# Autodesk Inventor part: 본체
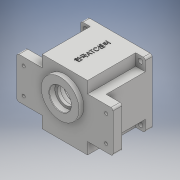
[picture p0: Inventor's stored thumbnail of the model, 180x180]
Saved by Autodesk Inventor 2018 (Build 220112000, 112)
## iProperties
Created: 2020-07
Part Number: 본체
Material: 일반
Document SubType Name: Modeling
Designer: admin
Density: 1 g/cm^3
Appearance: 기본값
Author: admin
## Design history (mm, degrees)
sketch "스케치1"
  geometry: L1 (65.8, 0)-(-65.8, 0) reference; L2 (0, -65.8)-(0, 65.8) reference; L3 (47, -47)-(-47, -47); L4 (-47, -47)-(-47, 47); L5 (-47, 47)-(47, 47); L6 (47, 47)-(47, -47); L7 (47, -47)-(-47, 47); L8 (-47, -47)-(47, 47); 1 further point
  constraints: 12 end point, 2 midpoint, 2 parallel, 1 horizontal, 1 perpendicular
  dimensions: "d0" = 94 distance of L4.end L5.end; "d1" = 94 distance of L3.end L4.end
extrude "돌출1" new body sketch "스케치1" stored distance "d2" = 67; taper "d3" = 0 deg
sketch "스케치2"
  geometry: L1 (47, -47)-(-47, -47) reference; L2 (-47, -47)-(-47, 47) reference; L3 (-47, 47)-(47, 47) reference; L4 (47, 47)-(47, -47) reference; L5 (-98, 0)-(98, 0) reference; L6 (0, -65.8)-(0, 65.8) reference; L7 (33, -47)-(-33, -47); L8 (-33, 47)-(33, 47); L9 (33, -47)-(-33, 47); L10 (-33, -47)-(33, 47); L11 (-70, -30)-(-70, 30); L12 (70, 30)-(70, -30); L13 (70, -30)-(-70, 30); L14 (-70, -30)-(70, 30); L15 (-70, 30)-(-33, 30); L16 (33, 30)-(70, 30); L17 (33, 47)-(33, 30); L18 (33, -30)-(33, -47); L19 (70, -30)-(33, -30); L20 (-33, -30)-(-70, -30); L21 (-33, -47)-(-33, -30); L22 (-33, 30)-(-33, 47); 1 further point
  constraints: 32 end point, 10 parallel, 4 midpoint, 4 perpendicular, 3 horizontal, 4 other
  dimensions: "d4" = 66 distance of L8.start L8.end; "d5" = 94 distance of L7.end L8.start; "d6" = 140 distance of L11.end L12.start; "d7" = 60 distance of L11.start L11.end
extrude "돌출3" join sketch "스케치2" distance "d10" = 13; taper "d11" = 0 deg
sketch "스케치5"
  geometry: L1 (-33, -47)-(33, -47) reference; L2 (33, -47)-(33, -30) reference; L3 (33, -30)-(70, -30) reference; L4 (70, -30)-(70, 30) reference; L5 (70, 30)-(33, 30) reference; L6 (33, 30)-(33, 47) reference; L7 (33, 47)-(-33, 47) reference; L8 (-33, 47)-(-33, 30) reference; L9 (-33, 30)-(-70, 30) reference; L10 (-70, 30)-(-70, -30) reference; L11 (-70, -30)-(-33, -30) reference; L12 (-33, -30)-(-33, -47) reference; L13 (-98, 0)-(98, 0) reference; L14 (0, -65.8)-(0, 65.8) reference; L15 (47, -47)-(-47, -47) reference; L16 (-47, -47)-(-47, 47) reference; L17 (-47, 47)-(47, 47) reference; L18 (47, 47)-(47, -47) reference; L19 (-47, 47)-(47, 47) reference; L20 (-47, 47)-(-33, 47); L21 (-33, 47)-(-33, 30); L22 (-33, 30)-(-47, 30); L23 (-47, 30)-(-47, 47); L24 (33, 47)-(47, 47); L25 (47, 47)-(47, 30); L26 (47, 30)-(33, 30); L27 (33, 30)-(33, 47); L28 (47, -47)-(-47, -47) reference; L29 (33, -30)-(47, -30); L30 (47, -30)-(47, -47); L31 (47, -47)-(33, -47); L32 (33, -47)-(33, -30); L33 (-47, -47)-(-47, 47) reference; L34 (-47, -30)-(-33, -30); L35 (-33, -30)-(-33, -47); L36 (-33, -47)-(-47, -47); L37 (-47, -47)-(-47, -30); 1 further point
  constraints: 32 end point, 8 parallel, 4 horizontal, 4 perpendicular, 4 point on line
extrude "돌출4" cut sketch "스케치5" distance "d12" = 57; taper "d13" = 0 deg
sketch "스케치6"
  geometry: L1 (47, 47)-(-47, 47) reference; L2 (-47, 47)-(-47, -47) reference; L3 (-47, -47)-(47, -47) reference; L4 (47, -47)-(47, 47) reference; L5 (-65.8, 0)-(65.8, 0) reference; L6 (0, 65.8)-(0, -65.8) reference; C1 r 40 at (0, 0); 1 further point
  constraints: 1 centre point, 1 coincident
  dimensions: "d14" = 80 diameter of C1
extrude "돌출5" cut sketch "스케치6" distance "d15" = 71; taper "d16" = 0 deg
sketch "스케치8"
  geometry: L1 (47, 47)-(-47, 47) reference; L2 (-47, 47)-(-47, -47) reference; L3 (-47, -47)-(47, -47) reference; L4 (47, -47)-(47, 47) reference; L5 (-98, 0)-(98, 0) reference; L6 (0, 65.8)-(0, -65.8) reference; C1 r 40 at (0, 0) reference; C2 r 21 at (0, -11); C3 r 15 at (0, 20); 1 further point
  constraints: 2 centre point, 2 point on line
  dimensions: "d22" = 42 diameter of C2; "d23" = 30 diameter of C3; "d24" = 11 distance from line of L5 C2.centre; "d25" = 20 distance of C3.centre point (0, 0)
extrude "돌출6" join sketch "스케치8" distance "d26" = 7; taper "d27" = 0 deg
sketch "스케치9"
  geometry: L1 (0, 65.8)-(0, -65.8) reference; L2 (-98, 0)-(98, 0) reference; C1 r 17.5 at (0, -11); A1 r 21 centre (0, -11) between (-8.978, 7.984) and (8.978, 7.984) reference; A2 r 15 centre (0, 20) between (8.978, 7.984) and (-8.978, 7.984) reference; 1 further point
  constraints: 1 centre point, 1 coincident
  dimensions: "d28" = 35 diameter of C1
extrude "돌출7" cut sketch "스케치9" distance "d29" = 10; taper "d30" = 0 deg
sketch "스케치10"
  geometry: L1 (-33, -47)-(33, -47) reference; L2 (33, -47)-(33, -30) reference; L3 (33, -30)-(70, -30) reference; L4 (70, -30)-(70, 30) reference; L5 (70, 30)-(33, 30) reference; L6 (33, 30)-(33, 47) reference; L7 (33, 47)-(-33, 47) reference; L8 (-33, 47)-(-33, 30) reference; L9 (-33, 30)-(-70, 30) reference; L10 (-70, 30)-(-70, -30) reference; L11 (-70, -30)-(-33, -30) reference; L12 (-33, -30)-(-33, -47) reference; L13 (-98, 0)-(98, 0) reference; L14 (0, -65.8)-(0, 65.8) reference; C1 r 17.5 at (0, 11) reference; C2 r 27.5 at (0, 11); A1 r 21 centre (0, 11) between (8.978, -7.984) and (-8.978, -7.984) reference; A2 r 15 centre (0, -20) between (-8.978, -7.984) and (8.978, -7.984) reference; 1 further point
  constraints: 1 centre point, 1 coincident
  dimensions: "d31" = 55 diameter of C2
extrude "돌출8" join sketch "스케치10" distance "d32" = 7; taper "d33" = 0 deg
sketch "스케치11"
  geometry: L1 (0, 76.8)-(0, -54.8) reference; L2 (-98, 11)-(98, 11) reference; C1 r 17.5 at (0, 0) reference; C2 r 40 at (0, 11) reference; C3 r 12.5 at (0, 0); A1 r 21 centre (0, 0) between (-8.978, 18.984) and (8.978, 18.984) reference; A2 r 15 centre (0, 31) between (8.978, 18.984) and (-8.978, 18.984) reference; A3 r 21 centre (0, 0) between (-8.978, 18.984) and (8.978, 18.984) reference; A4 r 15 centre (0, 31) between (8.978, 18.984) and (-8.978, 18.984) reference; 1 further point
  constraints: 1 centre point, 1 coincident
  dimensions: "d34" = 25 diameter of C3
extrude "돌출9" cut sketch "스케치11" extent not by distance; stored distance "d35" = 7; taper "d36" = 0 deg
sketch "스케치12"
  geometry: L1 (0, -76.8)-(0, 54.8) reference; L2 (-98, -11)-(98, -11) reference; C1 r 12.5 at (0, 0) reference; C2 r 27.5 at (0, 0) reference; C3 r 16 at (0, 0); 1 further point
  constraints: 1 centre point, 1 coincident
  dimensions: "d37" = 32 diameter of C3
extrude "돌출10" cut sketch "스케치12" distance "d38" = 8.3; taper "d39" = 0 deg
sketch "스케치13"
  geometry: L1 (47, 47)-(-47, 47) reference; L2 (-47, 47)-(-47, -47) reference; L3 (-47, -47)-(47, -47) reference; L4 (47, -47)-(47, 47) reference; L5 (-98, 0)-(98, 0) reference; L6 (0, 65.8)-(0, -65.8) reference; C1 r 17.5 at (0, -11) reference; C2 r 40 at (0, 0) reference; C3 r 11 at (0, 20); A1 r 21 centre (0, -11) between (-8.978, 7.984) and (8.978, 7.984) reference; A2 r 15 centre (0, 20) between (8.978, 7.984) and (-8.978, 7.984) reference; 1 further point
  constraints: 1 centre point, 1 coincident
  dimensions: "d40" = 22 diameter of C3
extrude "돌출11" cut sketch "스케치13" distance "d41" = 7; taper "d42" = 0 deg
sketch "스케치14"
  geometry: L1 (-98, -20)-(98, -20) reference; L2 (0, 45.8)-(0, -85.8) reference; C1 r 11 at (0, 0) reference; C2 r 11 at (0, 0) reference; C3 r 17.5 at (0, -31) reference; C4 r 9.5 at (0, 0); A1 r 21 centre (0, -31) between (-8.978, -12.016) and (8.978, -12.016) reference; A2 r 15 centre (0, 0) between (8.978, -12.016) and (-8.978, -12.016) reference; 1 further point
  constraints: 1 centre point, 1 coincident
  dimensions: "d43" = 19 diameter of C4
extrude "돌출12" cut sketch "스케치14" distance "d44" = 3; taper "d45" = 0 deg
sketch "스케치15"
  geometry: L1 (47, 47)-(-47, 47) reference; L2 (-47, 47)-(-47, -47) reference; L3 (-47, -47)-(47, -47) reference; L4 (47, -47)-(47, 47) reference; L5 (-98, 0)-(98, 0) reference; L6 (0, 65.8)-(0, -65.8) reference; C1 r 40 at (0, 0) reference; C2 r 43 at (0, 0); 1 further point
  constraints: 1 centre point, 1 coincident
  dimensions: "d46" = 86 diameter of C2
extrude "돌출13" cut sketch "스케치15" distance "d47" = 9; taper "d48" = 0 deg
sketch "스케치16" dims "d50" = 72
  geometry: L1 (47, 47)-(-47, 47) reference; L2 (-47, 47)-(-47, -47) reference; L3 (-47, -47)-(47, -47) reference; L4 (47, -47)-(47, 47) reference; L5 (-98, 0)-(98, 0) reference; L6 (0, 65.8)-(0, -65.8) reference; L7 (47, -4)-(36, -4); L8 (47, 4)-(36, 4); L9 (47, -4)-(47, 4); L10 (-47, -4)-(-36, -4); L11 (-47, 4)-(-36, 4); L12 (-47, -4)-(-47, 4); C1 r 43 at (0, 0) reference; A1 r 4 centre (36, 0) between (36, 4) and (36, -4); A2 r 4 centre (-36, 0) between (-36, -4) and (-36, 4); 2 further points
  constraints: 12 end point, 5 symmetric about line, 4 point on circle, 2 centre point, 2 collinear, 2 tangent, 1 coincident, 1 horizontal, 1 horizontal alignment, 1 parallel, 1 point on line, 1 vertical, 3 other
  dimensions: "d51" = 8 diameter of A1
extrude "돌출14" join sketch "스케치16" stored distance "d52" = 9; taper "d53" = 0 deg
sketch "스케치18"
  geometry: L1 (80, -10)-(94, -10) reference; L2 (94, 0)-(94, -10) reference; L3 (0, 0)-(94, 0) reference; L4 (0, 0)-(0, -10) reference; L5 (0, -10)-(14, -10) reference; L6 (14, -10)-(14, -80) reference; L7 (80, -80)-(14, -80) reference; L8 (80, -80)-(80, -10) reference; L9 (-51, -33.5)-(145, -33.5) reference; L10 (47, -104.4)-(47, 17.4) reference; 2 further points
  constraints: 1 point on line, 1 other
  dimensions: "d54" = 40 distance from line of L3 point (47, -40)
feature "엠보싱1" sketch "스케치18" dims "d0" = 94, "d1" = 94, "d55" = 0.5, "d56" = 0
sketch "스케치19"
  geometry: L1 (47, 30)-(47, -30) reference; L2 (47, -30)-(70, -30) reference; L3 (70, -30)-(70, 30) reference; L4 (70, 30)-(47, 30) reference; L5 (-47, -30)-(-47, 30) reference; L6 (-47, 30)-(-70, 30) reference; L7 (-70, 30)-(-70, -30) reference; L8 (-70, -30)-(-47, -30) reference; L9 (-98, 0)-(98, 0) reference; L10 (0, 65.9)-(0, -66.4) reference; L11 (-60, 19)-(60, 19); L12 (60, 19)-(60, -19); L13 (60, -19)-(-60, -19); L14 (-60, -19)-(-60, 19); L15 (-60, 19)-(60, -19); L16 (60, 19)-(-60, -19); C1 r 5 at (60, -19); C2 r 5 at (60, 19); C3 r 5 at (-60, -19); C4 r 5 at (-60, 19); 1 further point
  constraints: 12 end point, 4 centre point, 4 coincident, 2 midpoint, 2 parallel, 1 horizontal, 1 perpendicular
  dimensions: "d58" = 120 distance of L12.end L13.end; "d59" = 38 distance of L11.end L12.end; "d60" = 10 diameter of C1; "d61" = 10 diameter of C2; "d62" = 10 diameter of C3; "d63" = 10 diameter of C4
extrude "돌출15" cut sketch "스케치19" distance "d64" = 5; taper "d65" = 0 deg
sketch "스케치20"
  geometry: L1 (-13, 49)-(-13, -11) reference; L2 (-13, -11)-(10, -11) reference; L3 (10, -11)-(10, 49) reference; L4 (10, 49)-(-13, 49) reference; L5 (-107, -11)-(-107, 49) reference; L6 (-107, 49)-(-130, 49) reference; L7 (-130, 49)-(-130, -11) reference; L8 (-130, -11)-(-107, -11) reference; L9 (-158, 19)-(38, 19) reference; L10 (-60, 84.9)-(-60, -47.4) reference; C1 r 5 at (0, 0) reference; C2 r 5 at (0, 38) reference; C3 r 5 at (-120, 0) reference; C4 r 5 at (-120, 38) reference; C5 r 2.25 at (0, 0); C6 r 2.25 at (-120, 0); C7 r 2.25 at (0, 38); C8 r 2.25 at (-120, 38); 1 further point
  constraints: 4 centre point, 1 coincident, 1 horizontal, 1 vertical, 6 other
  dimensions: "d66" = 4.5 diameter of C5; "d69" = 120 distance of C5.centre C6.centre; "d72" = 38 distance of C5.centre C7.centre
extrude "돌출16" cut sketch "스케치20" stored distance "d75" = 5; taper "d76" = 0 deg
sketch "스케치21"
  geometry: L1 (36, 4)-(39.799, 4) reference; L2 (39.799, -4)-(36, -4) reference; L3 (-39.799, -4)-(-36, -4) reference; L4 (-36, 4)-(-39.799, 4) reference; C1 r 43 at (0, 0) reference; A1 r 4 centre (36, 0) between (36, 4) and (36, -4) reference; A2 r 40 centre (0, 0) between (-39.799, -4) and (39.799, -4) reference; A3 r 4 centre (-36, 0) between (-36, -4) and (-36, 4) reference; A4 r 40 centre (0, 0) between (39.799, 4) and (-39.799, 4) reference; 3 further points
  constraints: 2 coincident
hole "구멍1" sketch "스케치21" at (-36, 0), (36, 0) diameter "d77" = 3.242; stored, may be unused: countersink angle "d81" = 90 deg, drill point angle "d83" = 118 deg; dims "d78" = 7, "d79" = 4, "d80" = 2, "d82" = 9
sketch "스케치22"
  geometry: L1 (47, 47)-(-47, 47) reference; L2 (-47, 47)-(-47, -47) reference; L3 (-47, -47)-(47, -47) reference; L4 (47, -47)-(47, 47) reference; L5 (-98, 0)-(98, 0) reference; L6 (0, 65.9)-(0, -66.4) reference; L7 (-40, -40)-(40, -40); L8 (40, -40)-(40, 40); L9 (40, 40)-(-40, 40); L10 (-40, 40)-(-40, -40); L11 (-40, -40)-(40, 40); L12 (40, -40)-(-40, 40); C1 r 43 at (0, 0) reference; C2 r 3.5 at (-40, -40); C3 r 3.5 at (-40, 40); C4 r 3.5 at (40, 40); C5 r 3.5 at (40, -40); 1 further point
  constraints: 12 end point, 4 centre point, 4 coincident, 2 midpoint, 2 parallel, 1 horizontal, 1 perpendicular
  dimensions: "d84" = 80 distance of L9.end L8.end; "d85" = 80 distance of L8.end L7.end; "d86" = 7 diameter of C2; "d87" = 7 diameter of C3; "d88" = 7 diameter of C4; "d89" = 7 diameter of C5
extrude "돌출17" cut sketch "스케치22" stored distance "d90" = 5; taper "d91" = 0 deg
chamfer "모따기1" distance "d92" = 0.8; stored, may be unused: second distance "d93" = 2, angle "d94" = 30 deg
fillet "모깎기1" dims "d95" = 3
chamfer "모따기2" distance "d96" = 1; stored, may be unused: second distance "d97" = 2, angle "d98" = 30 deg
node "솔리드1"
node "투영된 루프1"
node "투영된 루프7"
node "투영된 루프8"
node "투영된 루프9"
node "투영된 루프12"
node "투영된 루프13"
node "투영된 루프14"
node "투영된 루프15"
node "투영된 루프16"
node "투영된 루프17"
node "투영된 루프18"
node "투영된 루프19"
node "투영된 루프20"
node "투영된 루프21"
node "투영된 루프22"
node "투영된 루프23"
node "투영된 루프24"
node "투영된 루프25"
node "투영된 루프26"
node "투영된 루프27"
node "투영된 루프28"
node "투영된 루프29"
node "투영된 루프30"
